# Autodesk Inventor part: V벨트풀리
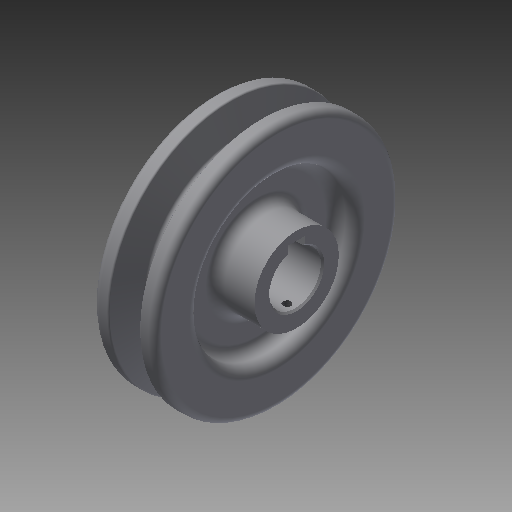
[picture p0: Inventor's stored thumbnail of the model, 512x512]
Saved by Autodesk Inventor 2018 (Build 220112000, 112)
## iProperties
Created: 2015-11
Part Number: V벨트풀리
Material: 강철, 탄소
Document SubType Name: Modeling
Designer: mduedu
Density: 1 g/cm^3
Appearance: 기본값
Author: mduedu
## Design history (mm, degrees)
sketch "스케치1"
  geometry: L1 (-9.5, 0)-(9.5, 0); L2 (0, 0)-(0, 37.7); L3 (-4.825, 37.7)-(-9.5, 37.7); L4 (-9.5, 37.7)-(-9.5, 0); L5 (0, 28.7)-(-2.074, 28.7); L6 (-2.074, 28.7)-(-4.825, 37.7); L7 (4.825, 37.7)-(9.5, 37.7); L8 (9.5, 37.7)-(9.5, 0); L9 (0, 28.7)-(2.074, 28.7); L10 (2.074, 28.7)-(4.825, 37.7); L11 (-9.5, 35)-(9.5, 35); 3 further points
  constraints: 22 end point, 7 point on line, 4 perpendicular, 3 symmetric about line, 1 coincident, 1 horizontal, 1 horizontal alignment, 1 midpoint, 1 vertical
  dimensions: "d0" = 19 distance of L1.start L1.end; "d2" = 75.4 diameter of L2.end L1 (derived); "d3" = 34 deg angle of L10 L6; "d4" = 6.3 distance between parallel lines of L11 L9; "d5" = 2.7 distance between parallel lines of L7 L11; "d6" = 8 distance of point (4, 35) point (-4, 35); "d7" = 70 diameter of L11 L1
revolve "회전1" sketch "스케치1" stored, may be unused: angle "d8" = 90 deg
sketch "스케치2"
  geometry: C1 r 24 at (0, 0); C2 r 13 at (0, 0); 1 further point
  constraints: 2 centre point, 2 coincident
  dimensions: "d9" = 48 diameter of C1; "d10" = 26 diameter of C2
extrude "돌출1" cut sketch "스케치2" distance "d11" = 6; taper "d12" = 0 deg
extrude "돌출3" join sketch "스케치2" distance "d37" = 6; taper "d38" = 0 deg
fillet "모깎기1" dims "d13" = 3
fillet "모깎기2" dims "d14" = 3
fillet "모깎기3" dims "d15" = 1, "d16" = 0.5, "d17" = 2
hole "구멍1" diameter "d20" = 16; stored, may be unused: countersink angle "d24" = 90 deg, drill point angle "d26" = 118 deg; dims "d21" = 6, "d22" = 4, "d23" = 2, "d25" = 8, "d53" = 10, "d54" = 10
sketch "스케치3"
  geometry: L1 (-2.5, 0)-(2.5, 0); L2 (2.5, 0)-(2.5, 10.3); L3 (2.5, 10.3)-(-2.5, 10.3); L4 (-2.5, 10.3)-(-2.5, 0); 2 further points
  constraints: 8 end point, 2 parallel, 1 coincident, 1 horizontal, 1 midpoint, 1 perpendicular
  dimensions: "d27" = 5 distance of L2.end L3.end; "d29" = 10.3 distance of L3.end L1.start
extrude "돌출2" cut sketch "스케치3" extent not by distance; stored distance "d30" = 6; taper "d31" = 0 deg
node "작업 평면1"
sketch "스케치4"
  geometry: L1 (19, -27)-(19, 27) reference; 2 further points
  constraints: 1 horizontal alignment
  dimensions: "d52" = 22 distance from line of L1 point (-3, 0)
hole "구멍2" sketch "스케치4" at (-3, 0) diameter "d42" = 2.459; stored, may be unused: countersink angle "d46" = 90 deg, drill point angle "d48" = 118 deg; dims "d43" = 6, "d44" = 4, "d45" = 2, "d47" = 8
chamfer "모따기3" distance "d58" = 0.5; stored, may be unused: second distance "d59" = 2, angle "d60" = 45 deg
node "솔리드1"
mirror "대칭1"
